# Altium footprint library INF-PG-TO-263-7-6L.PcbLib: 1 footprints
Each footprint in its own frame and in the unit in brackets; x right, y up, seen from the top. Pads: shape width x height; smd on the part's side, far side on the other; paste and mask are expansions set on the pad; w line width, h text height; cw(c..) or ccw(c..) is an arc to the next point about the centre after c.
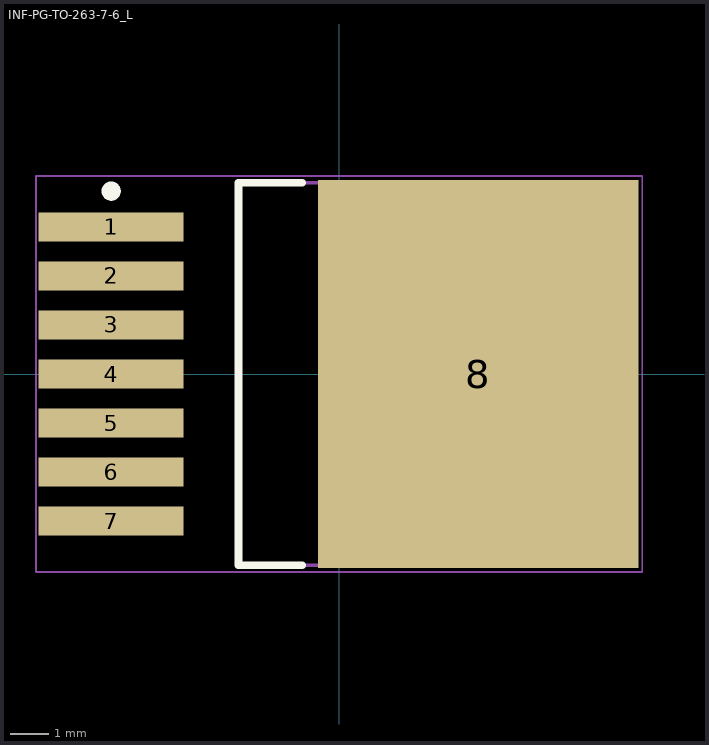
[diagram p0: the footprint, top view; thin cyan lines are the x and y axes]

## INF-PG-TO-263-7-6_L [mm] "DPAK, 7-Leads, Body 9.9x9.2mm, Pitch 1.27mm, IPC High Density"
height 4.4
pads (8):
  rect 3.75x0.75 smd: 1(-5.9,3.81) 2(-5.9,2.54) 3(-5.9,1.27) 4(-5.9,0) 5(-5.9,-1.27) 6(-5.9,-2.54) 7(-5.9,-3.81)
  rect 8.3x10.05 smd: 8(3.6,0)
Top Overlay:
  circle w0.25: c-5.9,4.735 r0.125
  lines w0.2: -0.95,-4.95 -2.6,-4.95 -2.6,4.95 -0.95,4.95
Mechanical 13:
  lines w0.1: -2.6,-4.95 6.8,-4.95 6.8,4.95 -2.6,4.95 -2.6,-4.95
Mechanical 15:
  lines w0.05: -7.85,-5.125 7.85,-5.125 7.85,5.125 -7.85,5.125 -7.85,-5.125
  lines w0.1: -0.5,0 0.5,0 ; 0,-0.5 0,0.5
3D body: height 4.4, standoff 0.1, extent -2.6,-4.95 6.8,4.95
